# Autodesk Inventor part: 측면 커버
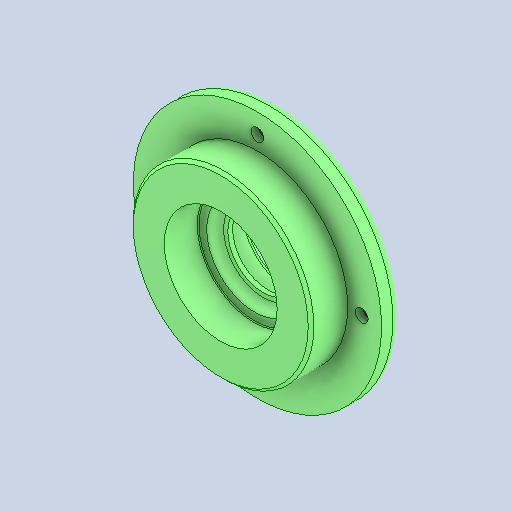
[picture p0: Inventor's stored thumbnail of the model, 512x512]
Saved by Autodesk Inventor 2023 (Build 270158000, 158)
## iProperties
Created: 2025-04
Part Number: 측면 커버
Material: 알루미늄 6061
Document SubType Name: Modeling
Designer: ADMIN_PC
Density: 2.71 g/cm^3
Appearance: 기본값
Company: 한국ATC센터
Author: jhkim
Revision Number: 1
Sending System: Autodesk Inventor 2026
Preprocessor: ST-DEVELOPER v20.1
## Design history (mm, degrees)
feature "솔리드1"
node "솔리드2"
